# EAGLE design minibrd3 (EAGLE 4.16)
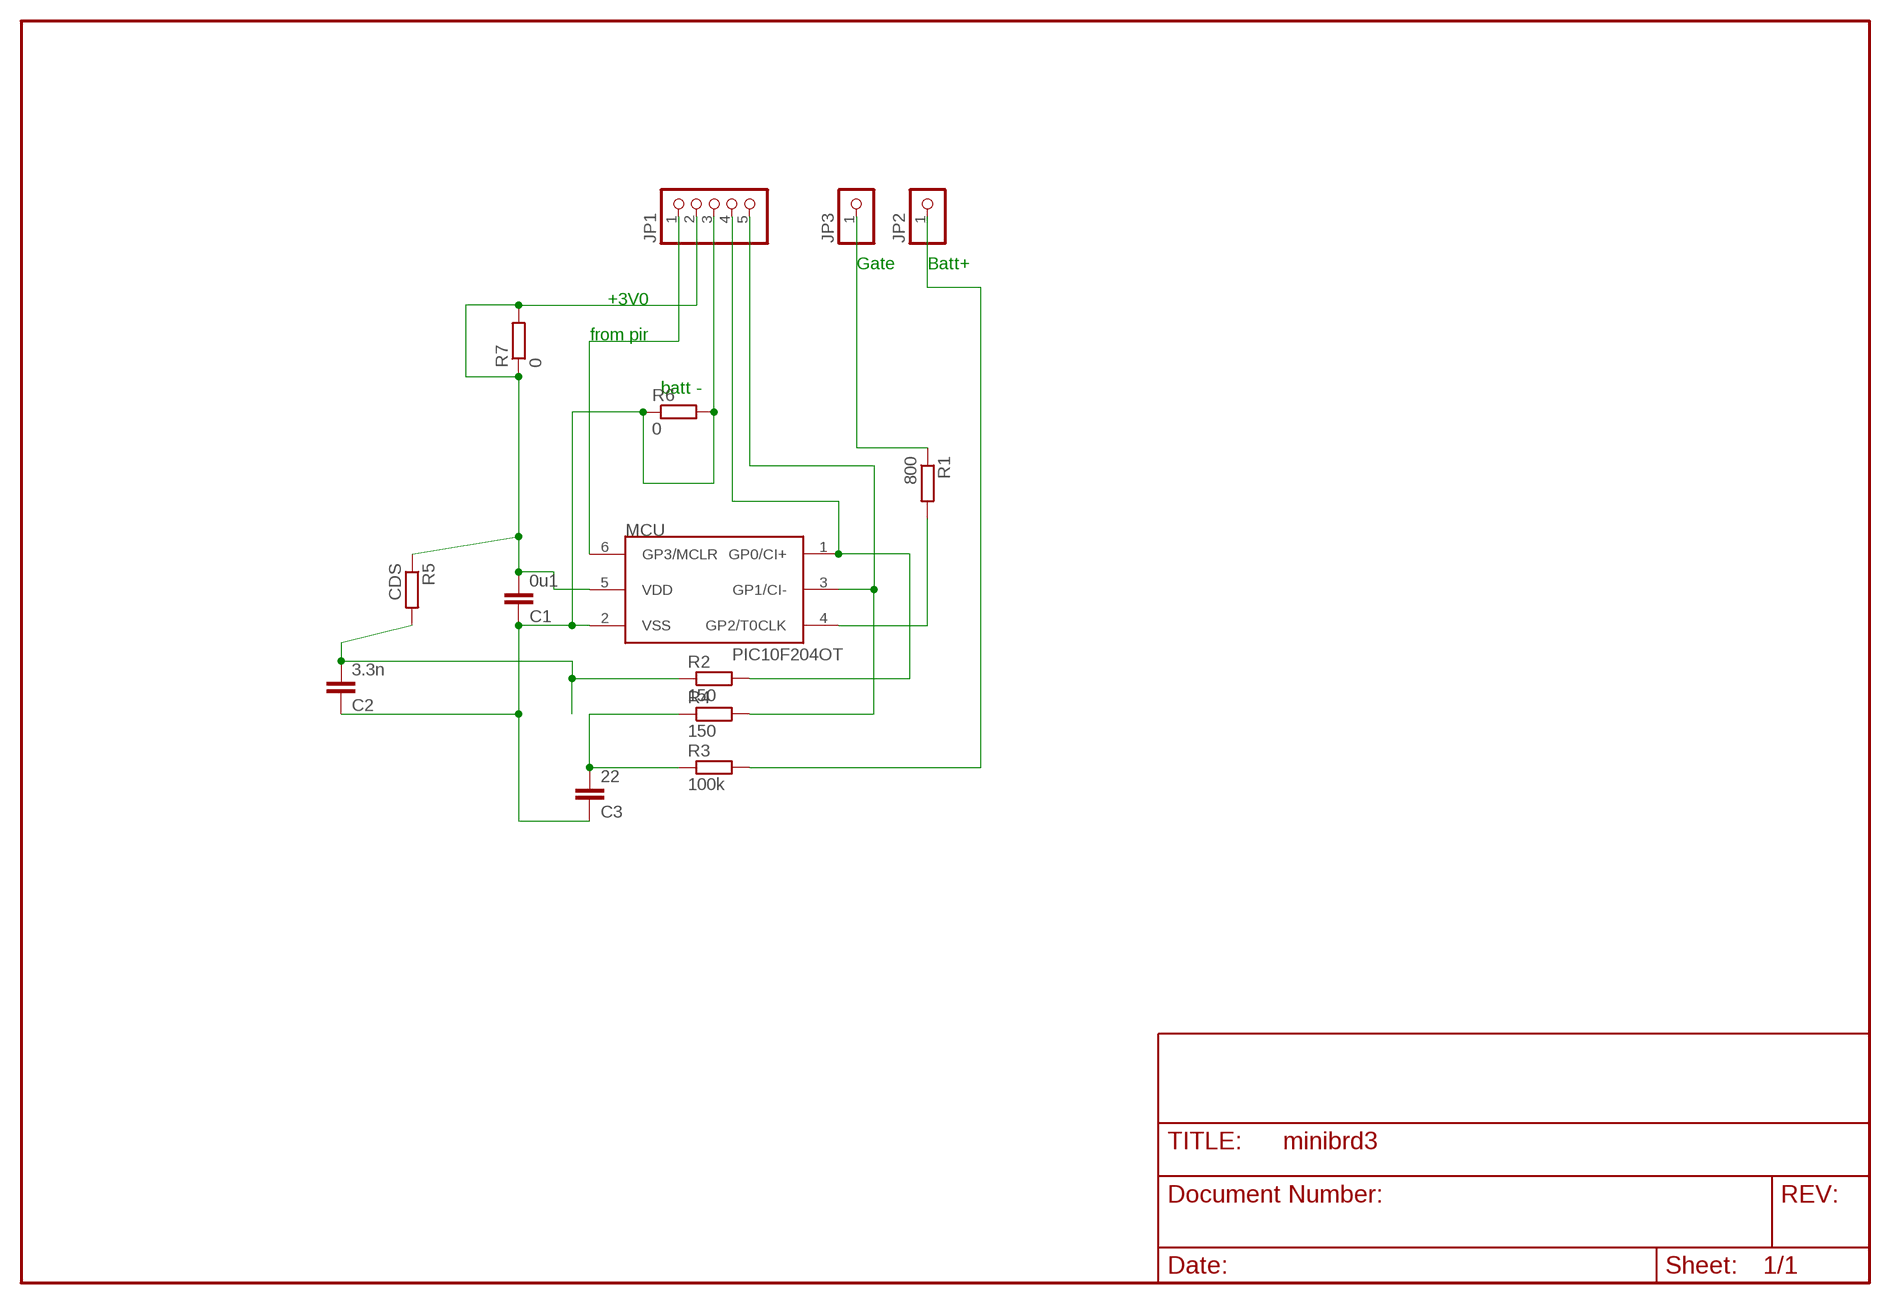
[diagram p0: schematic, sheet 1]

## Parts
C1  0u1  C-EUC1206  [C1206]
C2  3.3n  C-EUC1206  [C1206]
C3  22  C-EUC1206  [C1206]
JP1  PINHD-1X5  [1X05]
JP2  PINHD-1X1  [1X01]
JP3  PINHD-1X1  [1X01]
MCU  PIC10F204OT  [SOT23-6]
R1  800  R-EU_R1206  [R1206]
R2  150  R-EU_R1206  [R1206]
R3  100k  R-EU_R1206  [R1206]
R4  150  R-EU_R1206  [R1206]
R5  CDS  R-EU_0613/5V  [P0613V]
R6  0  R-EU_R1206  [R1206]
R7  0  R-EU_R1206  [R1206]

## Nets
N$1: JP3.1 R1.1
N$3: C2.2 R2.1 R5.2
N$4: JP1.4 MCU.1(GP0/CI+) R2.2
N$5: MCU.4(GP2/T0CLK) R1.2
N$7: C3.2 R3.1 R4.1
N$8: JP1.5 MCU.3(GP1/CI-) R4.2
PIR: JP1.1 MCU.6(GP3/MCLR)
V3: C1.2 JP1.2 MCU.5(VDD) R5.1 R7.1 R7.2
V+: JP2.1 R3.2
V-: C1.1 C2.1 C3.1 JP1.3 MCU.2(VSS) R6.1 R6.2

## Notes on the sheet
- Gate | Batt+
- +3V0
- from pir
- batt -

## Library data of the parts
C1-C3 = rcl:C-EU: CAPACITOR, European symbol
JP1 = pinhead:PINHD-1X5: PIN HEADER
JP2 JP3 = pinhead(2):PINHD-1X1: PIN HEADER
MCU = microchip-3:PIC10F2*: uPC nW 0,25/0,5k Program Flash memory Comparator
R1-R7 = rcl:R-EU_: RESISTOR, European symbol

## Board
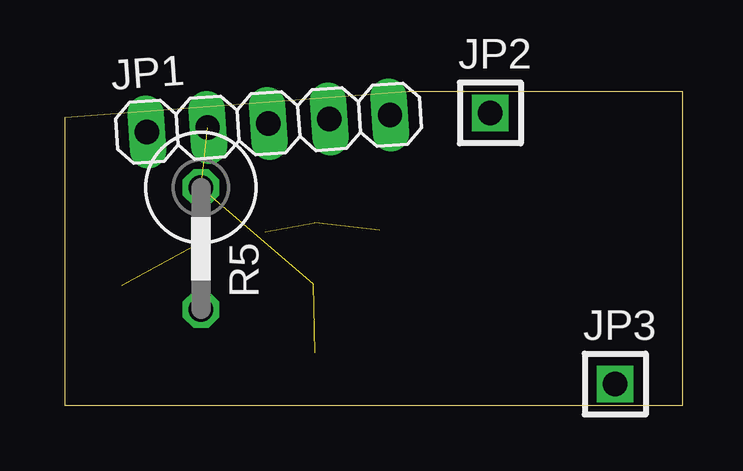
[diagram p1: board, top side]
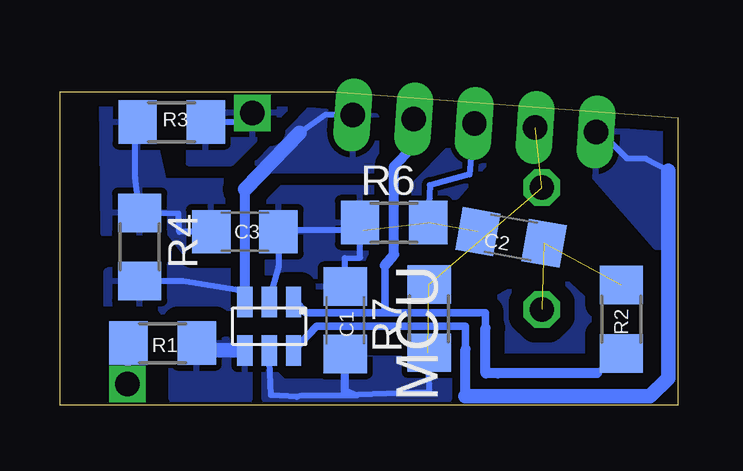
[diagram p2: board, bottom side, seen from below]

Size 25.77 x 13.08 mm. Coordinates in mm from the lower left corner, seen from the top.
Outline: 0,0 25.77,0 25.77,13.07 18,13.07 14.31,13.08 0,11.99 0,0
Copper layers (1*16): Top 0.035mm / dielectric 1.5mm / Bottom 0.035mm
Design rules "default": minimum track width 10mil, minimum drill 24mil, track to track 8mil, track to pad 8mil, pad to pad 8mil, via to via 8mil, smd to smd 8mil, copper to edge 1mil, drill to drill 8mil, minimum pad ring 10mil, minimum via ring 8mil, stop-mask expansion 4mil, vias tented up to drill 0mil, thermal gap 10mil

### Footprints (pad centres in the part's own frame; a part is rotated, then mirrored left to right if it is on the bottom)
C1206 = smd 1.6 x 1.8: 1 -1.4,0; 2 1.4,0
1X05 = drill 1.016 long: 1 -5.08,0; 2 -2.54,0; 3 0,0; 4 2.54,0; 5 5.08,0
1X01 = drill 1.016 square: 1 0,0
SOT23-6 = smd 0.635 x 1.27: 1 -1.016,-1.016; 2 0,-1.016; 3 1.016,-1.016; 4 1.016,1.016; 5 0,1.016; 6 -1.016,1.016
R1206 = smd 1.6 x 1.803: 1 -1.422,0; 2 1.422,0
P0613V = drill 1.016 octagon: 1 -2.54,0; 2 2.54,0

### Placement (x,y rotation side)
C1  13.88,3.55 270 bottom
C2  6.97,7 350 bottom
C3  18.06,7.23 180 bottom
JP1  8.49,11.75 4 top
JP2  17.74,12.19 0 top
JP3  22.95,0.88 0 top
MCU  17.04,3.3 180 bottom
R1  21.49,2.6 0 bottom
R2  2.36,3.59 270 bottom
R3  21.11,11.81 0 bottom
R4  22.44,6.6 270 bottom
R5  5.68,6.54 270 top
R6  11.84,7.62 0 bottom
R7  10.38,3.61 90 bottom

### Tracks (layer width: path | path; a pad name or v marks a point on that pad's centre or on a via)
N$1
  Bottom 0.254: R1.1 22.93,1.8 22.93,1.6 JP3.1
N$2
  pour Bottom: 9.49,10.92 9.49,10.73 11.01,9.2 11.01,8.06 11.07,8 9.99,8 9.36,8.69 9.23,8.69 8.03,10.09 7.84,10.79 8.15,11.11
N$3  (2 unrouted)
N$4
  Bottom 0.254: 15.9,4.31 MCU.1 | R2.2 3.38,1.34 | 11.09,10.74 JP1.4
  Bottom 0.305: 15.9,4.31 15.52,3.87 12.22,3.87 | 12.22,3.87 8.03,3.87 8.03,3.23 | 12.22,3.87 12.22,5.84
  Bottom 0.406: 12.22,5.84 11.84,6.28 11.84,9.96 11.09,10.74 | 3.38,1.34 7.52,1.33 8.03,1.33 8.03,3.23
N$5
  Bottom 0.254: MCU.4 18.28,2.29 | 20.28,2.29 R1.2
  Bottom 0.61: 18.28,2.29 20.28,2.29
  pour Bottom: 17.87,1.58 17.87,0.25 21.11,0.25 21.11,1.65 18.82,2.79 18.63,1.58
N$7
  Bottom 0.254: R3.1 22.63,10.99 22.63,9.49 R4.1 20.83,7.99 20.8,7.23 C3.2
  pour Bottom (isolate 0.61): 21.43,9.33 21.74,10.73 24.03,12.76 23.96,7.17 21.23,7.23 20.6,6.41 18.95,8.19 18.95,9.33
N$8
  Bottom 0.254: 13.56,12.12 13.55,12.12 | 13.56,12.12 JP1.5 | 15.77,11.36 14.69,12.12 13.56,12.12 | R4.2 20.64,5.18 18.33,4.79 MCU.3
  Bottom 0.406: MCU.3 18.06,9.01
  Bottom 0.61: 18.06,9.01 15.77,11.36
  pour Bottom (isolate 0.61): 18.76,5.84 23.33,5.84 23.84,5.58 23.84,4.12 23.71,3.93 18.76,3.93
  pour Bottom (isolate 0.61): 12.6,12.06 12.6,9.77 17.11,9.77 17.55,10.09 15.39,12.31
N$11
  pour Bottom (isolate 0.61): 5.3,5.71 7.58,4.44 7.58,1.9 4.34,1.9 3.71,2.41 3.71,4.25
PIR
  Bottom 0.254: 0.41,9.77 1.36,10.28 2.12,10.28 3.24,11.4 JP1.1
  Bottom 0.305: MCU.6 15.08,3.3 8.85,3.3 8.85,2.34
  Bottom 0.406: 8.85,0.38 8.85,2.34
  Bottom 0.61: 8.85,0.38 1.17,0.38 0.41,1.14 0.41,9.77
  pour Bottom (isolate 0.61): 0.28,11.81 2.57,12 3.77,10.47 3.58,9.65 0.91,6.6 0.22,6.6
V3  (3 unrouted)
  Bottom 0.254: MCU.5 16.97,0.42 15.89,0.35 15.69,0.41 13.39,0.41 13.86,0.63 C1.2 13.93,1.52 13.93,0.42 10.38,0.54 10.43,2.2 R7.1
  pour Bottom: 9.55,1.96 9.55,0.25 17.23,0.25 17.23,1.39 16.85,1.39 16.47,1.01 14.69,1.01 14.31,1.96
V+
  Bottom 0.254: R3.2 18.93,11.79 18.43,11.79 JP2.1
  pour Bottom (isolate 0.61): 16.03,12.82 20.41,12.82 20.41,10.09 18.63,10.09 16.15,12.57
V-  (2 unrouted)
  Bottom 0.254: MCU.2 16.98,4.63 16.66,5.78 C3.1 15.88,7.29 13.13,7.29 R6.1 13.25,6.16 13.89,6.14 C1.1 | R6.2 10.35,9.18 8.68,9.63 JP1.3
  pour Bottom (isolate 0.61): 12.53,9.08 12.53,4.44 15.07,4.44 15.84,5.52 17.3,5.52 17.3,9.08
